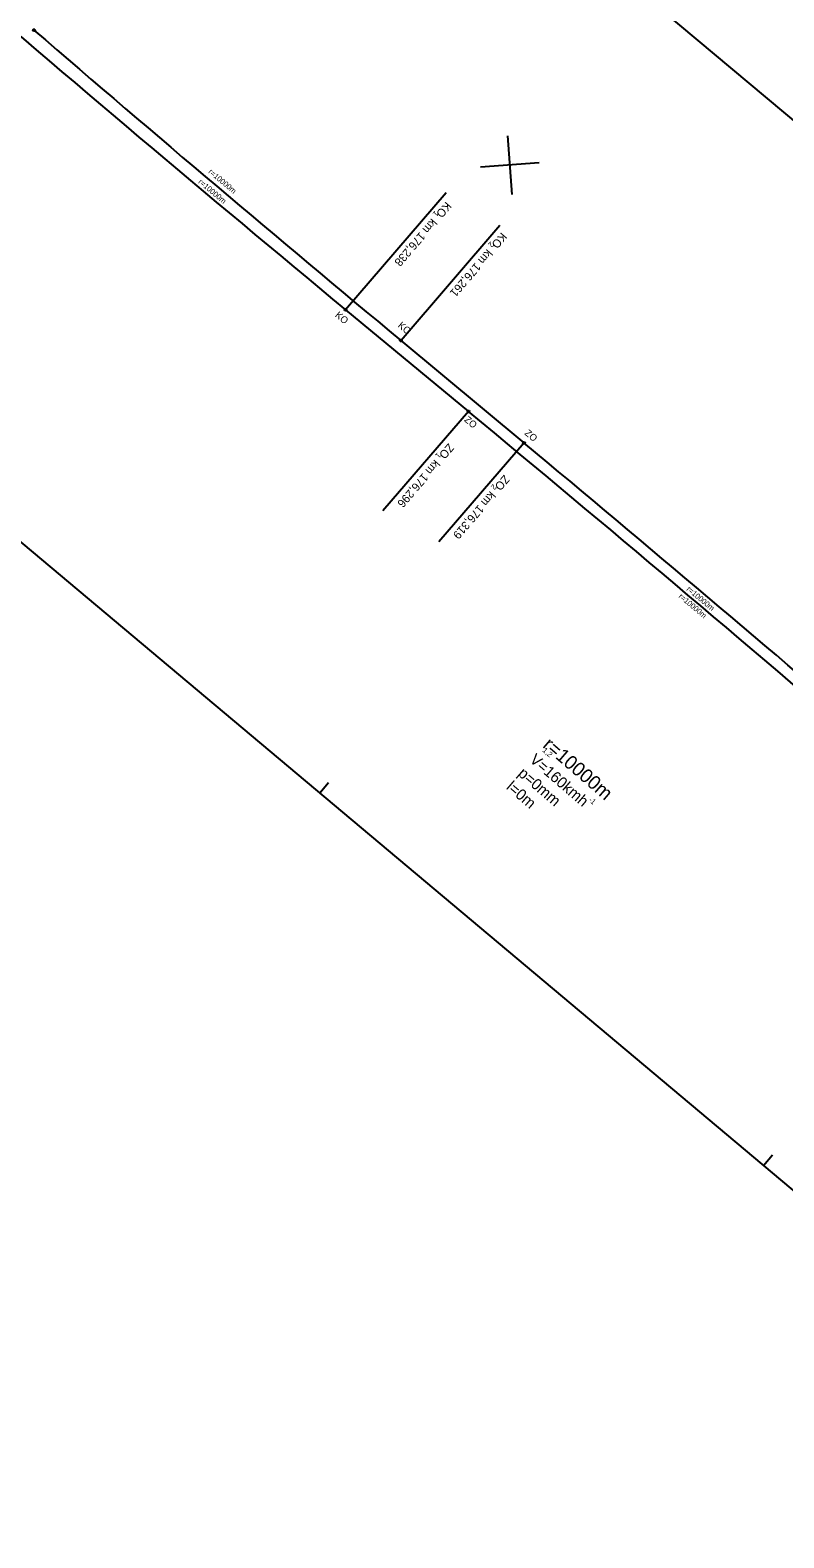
# Model space of a CAD drawing. Extents: x -473608 to -471381, y -1324122 to -1322275.
# Drawn here: x -472104 to -471831, y -1324122 to -1323576 of the extents above; entities that cross this region are included whole.
import ezdxf

# ---------------------------------------------------------------- set-up
doc = ezdxf.new("R2010")
doc.units = 0
for name, color, linetype in [('Level 1', 7, 'Continuous'), ('Level 11', 7, 'Continuous'), ('Level 61', 7, 'Continuous')]:
    doc.layers.add(name, color=color, linetype=linetype)

msp = doc.modelspace()

# ---------------------------------------------------------------- linework, layer by layer
at = {"layer": 'Level 1'}
for p, q in [((-472102.88, -1323575.85), (-472102.88, -1323575.85)), ((-471989.93, -1323677.18), (-471945.38, -1323714.04)), ((-471989.93, -1323677.18), (-471989.93, -1323677.18)), ((-471969.91, -1323688.33), (-471925.27, -1323725.43)), ((-471969.91, -1323688.33), (-471969.91, -1323688.33)), ((-471945.38, -1323714.04), (-471945.38, -1323714.04)), ((-471925.27, -1323725.43), (-471925.27, -1323725.43))]:
    msp.add_line(p, q, dxfattribs=at)
for points in [[(-472102.62, -1323575.55), (-472102.49, -1323575.92), (-472102.75, -1323576.23), (-472103.14, -1323576.15), (-472103.28, -1323575.77), (-472103.02, -1323575.47), (-472102.62, -1323575.55)], [(-471990.19, -1323677.48), (-471990.33, -1323677.11), (-471990.07, -1323676.8), (-471989.68, -1323676.87), (-471989.54, -1323677.25), (-471989.79, -1323677.55), (-471990.19, -1323677.48)], [(-471970.17, -1323688.63), (-471970.3, -1323688.26), (-471970.05, -1323687.95), (-471969.66, -1323688.02), (-471969.52, -1323688.4), (-471969.77, -1323688.7), (-471970.17, -1323688.63)], [(-471945.12, -1323713.74), (-471944.99, -1323714.11), (-471945.24, -1323714.42), (-471945.63, -1323714.35), (-471945.77, -1323713.97), (-471945.52, -1323713.67), (-471945.12, -1323713.74)], [(-471925.01, -1323725.12), (-471924.87, -1323725.5), (-471925.13, -1323725.8), (-471925.52, -1323725.74), (-471925.66, -1323725.36), (-471925.41, -1323725.05), (-471925.01, -1323725.12)]]:
    msp.add_lwpolyline(points, dxfattribs=at)
for centre, start, end in [((-465614.79, -1315972.79), 229.274753, 230.393272), ((-465578.53, -1315997.41), 229.274506, 230.272386), ((-478320.57, -1331418.39), 49.274722, 50.392906), ((-478316.81, -1331416.22), 49.274769, 50.271211)]:
    msp.add_arc(centre, 10000, start, end, dxfattribs=at)
at = {"layer": 'Level 11'}
for p, q in [((-471929.57, -1323635.4), (-471931.17, -1323614.09)), ((-471919.71, -1323623.94), (-471941.03, -1323625.55)), ((-471953.51, -1323634.81), (-471989.94, -1323677.16)), ((-471934.02, -1323646.66), (-471969.83, -1323688.29)), ((-471945.4, -1323714.01), (-471976.42, -1323750.08)), ((-471925.23, -1323725.46), (-471956.08, -1323761.32))]:
    msp.add_line(p, q, dxfattribs=at)
at = {"layer": 'Level 61'}
for p, q in [((-472612.76, -1322949.83), (-471486.68, -1323894.73)), ((-471677.59, -1324122.25), (-472803.67, -1323177.35)), ((-471999.32, -1323852.28), (-471996.11, -1323848.45)), ((-471838.46, -1323987.26), (-471835.24, -1323983.43))]:
    msp.add_line(p, q, dxfattribs=at)

# ---------------------------------------------------------------- texts
at = {"layer": 'Level 11'}
for s, height, rotation, p in [('r=10000m', 2, 320, (-472039.84, -1323627.47)), ('r=10000m', 2, 320, (-472043.49, -1323631.13)), ('KO  km 176,238', 3, 229.3, (-471953.54, -1323637.82)), ('1', 2, 229.3, (-471957.53, -1323641.19)), ('KO  km 176,261', 3, 229.3, (-471933.43, -1323648.95)), ('2', 2, 229.3, (-471937.43, -1323652.33)), ('KO', 2.5, 320, (-471993.94, -1323679.46)), ('KO', 2.5, 320, (-471971.2, -1323683.22)), ('ZO', 2.5, 320, (-471947.14, -1323717.37)), ('ZO', 2.5, 320, (-471925.27, -1323722.21)), ('ZO  km 176,296', 3, 229.3, (-471952.62, -1323725.39)), ('1', 2, 229.3, (-471956.62, -1323728.77)), ('ZO  km 176,319', 3, 229.3, (-471932.46, -1323736.84)), ('2', 2, 229.3, (-471936.46, -1323740.22)), ('r=10000m', 2, 320, (-471869.39, -1323781.35)), ('r=10000m', 2, 320, (-471866.52, -1323778.71)), ('1,2', 2, 319.3, (-471918.76, -1323837.12)), ('r=10000m', 5, 319.3, (-471918.78, -1323835.49)), ('V=160kmh', 4, 319.3, (-471923.49, -1323840.76)), ('l=0m', 4, 319.3, (-471931.97, -1323850.61)), ('p=0mm', 4, 319.3, (-471927.73, -1323845.69)), ('-1', 2, 319.3, (-471902.02, -1323855.1))]:
    msp.add_text(s, height=height, rotation=rotation, dxfattribs=at).set_placement(p)

doc.saveas('drawing.dxf')
